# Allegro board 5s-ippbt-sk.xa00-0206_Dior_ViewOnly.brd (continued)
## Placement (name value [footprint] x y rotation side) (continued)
PR236  -  [MX_R0402_SMALL_T01]  100.17 67.88 270 top
PR237  -  [MX_R0402_SMALL_T01]  99.43 64.37 90 bottom
PR238  -  [MX_R0402_SMALL_T01]  99.66 64.83 0 top
PR239  -  [MX_R0402_SMALL_T01]  97.63 79.31 0 bottom
PR240  -  [MX_R0402_SMALL_T01]  99.15 67.88 90 top
PR241  -  [MX_R0402_SHORT_SMALL]  98.01 64.19 0 bottom
PR242  -  [MX_R0402_SMALL_T01]  97.5 60.89 90 top
PR243  -  [MX_R0402_SMALL_T01]  101.95 64.32 270 top
PR244  -  [MX_R0402_SMALL_T01]  96.87 57.82 270 top
PR245  -  [MX_R0402_SMALL_T01]  101.44 65.57 180 top
PR247  -  [MX_R0402_SMALL_T01]  57.88 32.95 90 bottom
PRT1  -  [MX_R0402_SMALL_T01]  108.04 38.79 0 bottom
PRT2  -  [MX_R0402_SMALL_T01]  105 95.44 180 bottom
PRT3  -  [MX_R0402_SMALL_T01]  42 27.11 270 bottom
PRT4  -  [MX_R0402_SMALL_T01]  66.39 42.86 180 bottom
PRT5  -  [MX_R0402_SMALL_T01]  70.71 24.57 0 top
PT1  -  [MX_TPC26T_S4_68]  104.3 109.55 0 top
PT2  -  [MX_TPC26T_S4_68]  107.65 109.76 0 top
PT3  -  [MX_TPC26T_S4_68]  102.58 109.24 0 top
PT4  -  [MX_TPC26T_S4_68]  105.94 110.12 0 top
PT5  -  [MX_TPC26T_S4_68]  100.91 109.71 0 top
PT6  -  [MX_TPC26T_S4_68]  103.26 100.72 180 bottom
PT7  -  [MX_TPC26T_S4_68]  103.29 105.44 180 bottom
PT8  -  [MX_TPC26T_S4_68]  103.27 102.98 180 bottom
PT9  -  [MX_TPC26T_S4_68]  104.59 104.2 180 bottom
PT10  -  [MX_TPC26T_S4_68]  104.61 101.81 180 bottom
PU1  -  [MX_SOT89]  107.03 97.21 180 top
PU2  -  [MX_DFN_10P_20_S118_P_RI_2V]  97.5 103.06 180 top
PU3  -  [MX_QFN_20P_16_S118_PAD_4V]  13.3 32.83 270 bottom
PU4  -  [MX_SOIC_8P_50_197X236_PAD_R]  42.77 12.76 90 bottom
PU5  -  [MX_SOIC_8P_50_197X236_PAD_R]  99.15 19.74 90 bottom
PU6  -  [MX_SOIC_8P_50_197X236_PAD_R]  64.48 33.97 90 bottom
PU7  -  [MX_SO8_H69]  40.1 20.25 90 bottom
PU8  -  [MX_QFN_20P_16_S118_PAD_4V]  12.54 77.4 180 bottom
PU9  -  [MX_QFN_32P_16_S157_PAD_4V]  100.8 60.26 90 bottom
Q1  -  [MX_SOT23_H43]  19.78 59.88 180 bottom
Q2  -  [MX_SOT23_H43]  19.78 56.57 180 bottom
Q3  -  [MX_SOT363]  19.52 69.66 270 bottom
Q7  -  [MX_SOT23]  80.36 31.68 90 bottom
Q9  -  [MX_SOT23]  26.13 63.31 180 bottom
Q27  -  [MX_SOT23_TOREX_H57]  57.75 93.02 0 top
Q30  -  [MX_SOT23]  107.15 13.01 90 top
Q31  -  [MX_SOT23]  101.31 14.92 90 top
Q32  -  [MX_SOT23]  93.44 15.17 90 top
Q33  -  [MX_SOT23]  96.74 15.17 90 top
Q38  -  [MX_SOT23_H43]  64.74 81.47 90 top
Q39  -  [MX_SOT23_H43]  61.18 81.4 90 top
Q41  -  [MX_SOT23]  45.69 26.6 270 bottom
Q9414  -  [MX_SOT23_H43]  26.13 73.34 180 bottom
Q9415  -  [MX_SOT23_H43]  48.99 26.6 270 bottom
Q9416  -  [MX_SOT23_H43]  26.13 80.07 180 bottom
R1  -  [MX_R0402_SMALL_T01]  48.23 32.7 90 bottom
R2  -  [MX_R0402_SMALL_T01]  22.83 70.29 180 bottom
R3  -  [MX_R0402_SMALL_T01]  16.35 70.29 180 bottom
R4  -  [MX_R0402_SMALL_T01]  16.48 58.99 180 bottom
R5  -  [MX_R0402_SMALL_T01]  8.2 94.29 90 top
R6  -  [MX_R0402_SMALL_T01]  60.29 88.07 180 bottom
R7  -  [MX_R0402_SMALL_T01]  80.36 34.73 270 bottom
R8  -  [MX_R0402_SMALL_T01]  22.83 65.9 0 bottom
R9  -  [MX_R0402_SMALL_T01]  22.83 67.67 0 bottom
R10  -  [MX_R0402_SMALL_T01]  64.04 83.27 270 bottom
R11  -  [MX_R0402_SMALL_T01]  64.89 83.27 270 bottom
R13  -  [MX_R0402_SMALL_T01]  60.29 88.96 180 bottom
R14  -  [MX_R0402_SMALL_T01]  11.68 109.56 0 top
R15  -  [MX_R0402_SMALL_T01]  11.68 107.83 0 top
R16  -  [MX_R0402_SMALL_T01]  58.11 85.15 180 bottom
R17  -  [MX_R0402_SMALL_T01]  58.11 86.17 180 bottom
R18  -  [MX_R0402_SMALL_T01]  67.66 83.04 270 bottom
R19  -  [MX_R0402_SMALL_T01]  60.29 85.15 0 bottom
R20  -  [MX_R0402_SMALL_T01]  60.29 86.17 0 bottom
R21  -  [MX_R0402_SMALL_T01]  66.77 83.04 90 bottom
R22  -  [MX_R0402_SMALL_T01]  68.17 92.77 90 bottom
R23  -  [MX_R0402_SMALL_T01]  70.58 85.78 0 bottom
R24  -  [MX_R0402_SMALL_T01]  70.58 86.67 0 bottom
R25  -  [MX_R0402_SMALL_T01]  70.58 88.39 0 bottom
R26  -  [MX_R0402_SMALL_T01]  71.21 89.62 270 bottom
R30  -  [MX_R0402_SMALL_T01]  83.02 18.35 270 top
R89  -  [MX_R0402_SMALL_T01]  70.71 4.89 0 top
R90  -  [MX_R0402_SMALL_T01]  61.94 93.02 270 top
R91  -  [MX_R0402_SMALL_T01]  62.83 93.02 90 top
R92  -  [MX_R0603_SHORT_SMALL]  58.13 93.79 180 bottom
R93  -  [MX_R0402_SMALL_T01]  53.05 101.15 90 bottom
R95  -  [MX_R0402_SMALL_T01]  60.04 96.96 0 bottom
R96  -  [MX_R0402_SMALL_T01]  57.88 95.94 180 bottom
R97  -  [MX_R0402_SMALL_T01]  57.88 96.96 180 bottom
R109  -  [MX_R0402_SMALL_T01]  4.4 94.76 0 top
R149  -  [MX_R0402_SMALL_T01]  108.55 41.08 90 bottom
R153  -  [MX_R0402_SMALL_T01]  93.31 74.74 180 top
R159  -  [MX_R0402_SMALL_T01]  105.12 11.87 270 top
R160  -  [MX_R0402_SMALL_T01]  104.23 11.87 270 top
R169  -  [MX_R0402_SMALL_T01]  103.34 11.87 270 top
R170  -  [MX_R0402_SMALL_T01]  102.46 11.87 270 top
R176  -  [MX_R0402_SMALL_T01]  90.9 13.52 0 top
R182  -  [MX_R0402_SMALL_T01]  90.9 14.41 0 top
R184  -  [MX_R0402_SMALL_T01]  99.03 16.19 270 top
R188  -  [MX_R0402_SMALL_T01]  4.92 44.76 0 bottom
R191  -  [MX_R0402_SMALL_T01]  68.04 9.84 0 top
R192  -  [MX_R0402_SMALL_T01]  70.68 6.18 0 top
R197  -  [MX_R0402_SHORT_SMALL]  9.24 52.89 90 bottom
R198  -  [MX_R1206]  9.75 66.23 0 bottom
R199  -  [MX_R0402_SHORT_SMALL]  11.65 61.91 270 bottom
R200  -  [MX_R0402_SMALL_T01]  6.44 61.4 0 bottom
R205  -  [MX_R0603_SMALL_T01]  82.24 4.4 0 bottom
R207  -  [MX_R0402_SHORT_SMALL]  67.02 27.24 180 bottom
R209  -  [MX_R0603_SMALL_T01]  66.77 28.38 0 bottom
R212  -  [MX_R0402_SHORT_SMALL]  84.55 15.6 0 bottom
R213  -  [MX_R0402_SHORT_SMALL]  79.21 28.38 90 bottom
R214  -  [MX_R0402_SMALL_T01]  80.1 28.38 90 bottom
R215  -  [MX_R0402_SMALL_T01]  84.17 11.11 0 bottom
R216  -  [MX_R0402_SHORT_SMALL]  84.17 12.12 180 bottom
R221  -  [MX_R0402_SMALL_T01]  84.55 21.14 180 bottom
R222  -  [MX_R0402_SMALL_T01]  84.55 18.47 180 bottom
R224  -  [MX_R0402_SMALL_T01]  84.55 20.25 180 bottom
R225  -  [MX_R0402_SMALL_T01]  81.15 6.33 270 bottom
R226  -  [MX_R0402_SMALL_T01]  75.02 11.49 180 top
R227  -  [MX_R0402_SMALL_T01]  88.1 21.9 180 bottom
R228  -  [MX_R0402_SMALL_T01]  90.01 21.9 0 bottom
R229  -  [MX_SHORTPIN_RECTANGLE_LF3]  93.82 13.01 0 bottom
R230  -  [MX_R0402_SMALL_T01]  88.49 13.01 0 bottom
R233  -  [MX_R0402_SMALL_T01]  74.64 22.79 270 top
R234  -  [MX_R0402_SMALL_T01]  72.86 22.79 270 top
R243  -  [MX_R0402_SMALL_T01]  84.55 19.36 180 bottom
R244  -  [MX_R0402_SMALL_T01]  73.37 95.44 270 top
R250  -  [MX_R0402_SHORT_SMALL]  75.02 76.77 90 top
R251  -  [MX_R0402_SMALL_T01]  65.02 85.28 180 top
R252  -  [MX_R0402_SMALL_T01]  48.73 23.92 0 bottom
R330  -  [MX_R0402_SMALL_T01]  106.9 16.06 90 top
R332  -  [MX_R0402_SMALL_T01]  103.34 14.28 270 top
R357  -  [MX_R0402_SMALL_T01]  105.12 14.28 270 top
R368  -  [MX_R0402_SMALL_T01]  105.12 16.06 90 top
R370  -  [MX_R0402_SMALL_T01]  106.01 16.06 90 top
R371  -  [MX_R0402_SMALL_T01]  104.23 14.28 270 top
R3008  -  [MX_R0402_SMALL_T01]  73.5 28.25 270 bottom
R60208  -  [MX_R0402_SMALL_T01]  61.94 85.4 0 top
R60209  -  [MX_R0402_SMALL_T01]  61.94 84.51 0 top
R60212  -  [MX_R0402_SHORT_SMALL]  84.55 16.44 0 bottom
R60214  -  [MX_R0402_SMALL_T01]  4.92 43.87 0 bottom
R60215  -  [MX_R0402_SHORT_SMALL]  71.47 11.87 90 top
R60216  -  [MX_R0402_SMALL_T01]  18.9 31.07 90 bottom
R60217  -  [MX_R0402_SMALL_T01]  21.25 35.62 270 bottom
R60218  -  [MX_R0402_SMALL_T01]  82.9 40.57 270 top
R60219  -  [MX_R0402_SMALL_T01]  82.9 42.35 270 top
R60220  -  [MX_R0402_SMALL_T01]  69.82 40.45 270 top
R60221  -  [MX_R0402_SMALL_T01]  70.71 40.45 90 top
R60226  -  [MX_R0402_SMALL_T01]  22.83 66.79 0 bottom
R60290  -  [MX_R0402_SMALL_T01]  66.39 79.56 0 bottom
R60291  -  [MX_R0402_SHORT_SMALL]  63.39 8.7 180 bottom
R60293  -  [MX_R0402_SHORT_SMALL]  70.07 6.41 270 bottom
R60297  -  [MX_R0402_SMALL_T01]  22.95 32.32 0 bottom
R60298  -  [MX_R0402_SMALL_T01]  16.35 63.05 0 bottom
R60299  -  [MX_R0402_SMALL_T01]  22.83 62.42 0 bottom
R60302  -  [MX_R0402_SMALL_T01]  22.83 79.18 180 bottom
R60304  -  [MX_R0402_SMALL_T01]  22.83 56.12 0 bottom
R60306  -  [MX_R0402_SMALL_T01]  22.83 49.08 0 bottom
R60307  -  [MX_R0402_SMALL_T01]  21.43 31.12 90 bottom
R60308  -  [MX_R0402_SMALL_T01]  20.77 38.9 180 bottom
R60309  -  [MX_R0402_SMALL_T01]  22.83 75.88 180 bottom
R60310  -  [MX_R0402_SMALL_T01]  60.29 87.23 180 bottom
SC1  -  [MX_C0402_SMALL_T01]  90.14 54.42 90 top
SC2  -  [MX_C0402_SMALL_T01]  4.92 42.99 180 bottom
SC3  -  [MX_C0402_SMALL_T01]  90.52 58.23 180 top
SC4  -  [MX_C0402_SMALL_T01]  85.08 74.69 270 bottom
SC5  -  [MX_C0402_SMALL_T01]  84.29 77.66 180 bottom
SC6  -  [MX_C0402_SMALL_T01]  86.56 76.51 180 bottom
SC7  -  [MX_C0402_SMALL_T01]  22.95 34.73 0 bottom
SC8  -  [MX_C0402_SMALL_T01]  16.35 64.7 0 bottom
SC9  -  [MX_C0402_SMALL_T01]  87.85 52.51 0 top
SC10  -  [MX_C0402_SMALL_T01]  87.85 53.4 0 top
SC11  -  [MX_C0402_SMALL_T01]  52.54 28.38 90 top
SC12  -  [MX_C0402_SMALL_T01]  43.63 28.38 0 top
SC13  -  [MX_C0402_SMALL_T01]  53.31 24.95 180 top
SC14  -  [MX_C0402_SMALL_T01]  44.19 25.31 0 top
SC21  -  [MX_C0402_SMALL_T01]  4.41 58.35 0 bottom
SC22  -  [MX_C0402_SMALL_T01]  4.41 59.24 0 bottom
SC23  -  [MX_C0402_SMALL_T01]  86.45 13.01 180 bottom
SC24  -  [MX_C0402_SMALL_T01]  70.96 6.41 90 bottom
SC25  -  [MX_C0402_SMALL_T01]  72.97 6.44 90 bottom
SC26  -  [MX_C0402_SMALL_T01]  73.25 11.87 90 top
SC27  -  [MX_C0402_SMALL_T01]  74.19 76.77 270 top
SC33  -  [MX_C0402_SMALL_T01]  73.25 76.77 270 top
SC36  -  [MX_C0402_SMALL_T01]  22.83 59.11 0 bottom
SC65  -  [MX_C0402_SMALL_T01]  22.83 52.84 0 bottom
SC67  -  [MX_C0402_SMALL_T01]  22.83 60 0 bottom
SD1  -  [MX_SOT323]  5.3 40.83 270 bottom
SL1  -  [MX_R0603_SHORT_SMALL]  83.02 40.32 270 bottom
SL2  -  [MX_R0603_SHORT_SMALL]  64.52 40.32 270 top
SL3  -  [MX_R0603_SHORT_SMALL]  78.01 40.32 270 top
SL4  -  [MX_R0603_SHORT_SMALL]  71.77 50.02 180 top
SL5  -  [MX_R0603_SHORT_SMALL]  66.96 40.32 270 top
SL6  -  [MX_R0603_SHORT_SMALL]  90.52 61.91 180 bottom
SL7  -  [MX_R0603_SHORT_SMALL]  68.67 40.32 270 top
SL8  -  [MX_R0603_SHORT_SMALL]  90.52 60.64 0 bottom
SL9  -  [MX_R0603_SMALL_T01]  75.66 40.32 270 top
SL10  -  [MX_R0603_SMALL_T01]  73.12 40.32 270 top
SL11  -  [MX_R0603_SHORT_SMALL]  86.3 64.98 0 top
SL12  -  [MX_R0603_SMALL_T01]  65.74 40.32 270 top
SL13  -  [MX_R0603_SHORT_SMALL]  85.31 40.32 270 bottom
SL14  -  [MX_R0603_SHORT_SMALL]  74.13 59.11 270 top
SL15  -  [MX_R0603_SMALL_T01]  74.39 40.32 90 top
SL16  -  [MX_R0603_SHORT_SMALL]  78.58 62.42 180 top
SM_TP1  -  [MX_TPC26T_S4_68]  65.27 81.7 180 bottom
SR1  -  [MX_R0402_SMALL_T01]  50.41 29.9 90 bottom
SR2  -  [MX_R0402_SMALL_T01]  64.74 78.42 90 top
SR3  -  [MX_R0402_SMALL_T01]  75.15 95.18 180 bottom
SR4  -  [MX_R0402_SMALL_T01]  72.61 97.47 180 bottom
SR5  -  [MX_R0402_SMALL_T01]  49.88 32.7 270 bottom
SR6  -  [MX_R0402_SMALL_T01]  49.06 32.7 90 bottom
SR7  -  [MX_R0402_SMALL_T01]  46.19 32.7 270 bottom
SR8  -  [MX_R0402_SMALL_T01]  45.18 32.7 270 bottom
SR9  -  [MX_R0402_SMALL_T01]  44.16 32.7 90 bottom
SR10  -  [MX_R0402_SMALL_T01]  47.97 29.9 90 bottom
SR11  -  [MX_R0402_SMALL_T01]  46.96 29.9 90 bottom
SR12  -  [MX_R0402_SMALL_T01]  93.69 93.53 180 top
SR13  -  [MX_R0402_SMALL_T01]  93.69 94.42 0 top
SR14  -  [MX_R0402_SMALL_T01]  76.42 89.47 270 top
SR15  -  [MX_R0402_SMALL_T01]  16.35 69.4 180 bottom
SR16  -  [MX_R0402_SMALL_T01]  75.53 89.47 270 top
SR18  -  [MX_R0603_SMALL_T01]  90.39 59.88 270 top
SR21  -  [MX_R0402_SMALL_T01]  91.1 55.03 180 bottom
SR22  -  [MX_R0402_SMALL_T01]  90.52 57.03 180 bottom
SR24  -  [MX_R0402_SMALL_T01]  91.13 54.19 180 bottom
SR26  -  [MX_R0402_SMALL_T01]  90.52 57.9 180 bottom
SR28  -  [MX_R0402_SMALL_T01]  22.83 72.45 0 bottom
SR29  -  [MX_R0402_SMALL_T01]  22.83 73.34 180 bottom
SR30  -  [MX_R0402_SMALL_T01]  90.14 56.07 90 top
SR31  -  [MX_R0402_SMALL_T01]  90.52 57.34 0 top
SR32  -  [MX_R0402_SMALL_T01]  90.52 58.73 180 bottom
SR33  -  [MX_R0402_SMALL_T01]  90.52 59.62 180 bottom
SR34  -  [MX_R0402_SMALL_T01]  22.83 55.23 180 bottom
SR35  -  [MX_R0402_SHORT_SMALL]  22.83 74.23 0 bottom
SR36  -  [MX_R0402_SMALL_T01]  74.13 78.88 270 top
SR37  -  [MX_R0402_SMALL_T01]  75.91 78.88 270 top
SR41  -  [MX_R0402_SMALL_T01]  86.96 74.61 90 bottom
SR43  -  [MX_R0603_SMALL_T01]  71.98 77.02 90 bottom
SR44  -  [MX_R0402_SMALL_T01]  70.83 76.89 90 bottom
SR46  -  [MX_R0402_SMALL_T01]  81.93 76.77 90 bottom
SR47  -  [MX_R0402_SMALL_T01]  90.52 66.61 0 bottom
SR48  -  [MX_R0402_SMALL_T01]  73.7 76.77 90 bottom
SR49  -  [MX_R0402_SMALL_T01]  90.52 67.5 180 bottom
SR50  -  [MX_R0402_SMALL_T01]  74.59 76.77 90 bottom
SR52  -  [MX_R0402_SMALL_T01]  76.34 76.56 90 bottom
SR54  -  [MX_R0402_SMALL_T01]  75.48 76.56 90 bottom
SR55  -  [MX_R0402_SMALL_T01]  79.24 78.93 270 bottom
SR56  -  [MX_R0402_SMALL_T01]  77.56 78.93 90 bottom
SR57  -  [MX_R0402_SMALL_T01]  80.99 78.93 90 bottom
SR58  -  [MX_R0402_SMALL_T01]  78.4 78.93 90 bottom
SR59  -  [MX_R0402_SMALL_T01]  78.21 76.5 90 bottom
SR60  -  [MX_R0402_SMALL_T01]  80.15 76.77 90 bottom
SR61  -  [MX_R0402_SMALL_T01]  77.4 76.5 90 bottom
SR62  -  [MX_R0603_SMALL_T01]  78.99 76.46 90 top
SR63  -  [MX_R0603_SMALL_T01]  84.42 76.51 180 bottom
SR64  -  [MX_R0402_SMALL_T01]  86.56 77.66 0 bottom
SR65  -  [MX_R0402_SMALL_T01]  22.95 33.84 0 bottom
SR66  -  [MX_R0402_SMALL_T01]  22.95 35.75 0 bottom
SR67  -  [MX_R0402_SMALL_T01]  19.5 38.44 270 bottom
SR68  -  [MX_R0402_SMALL_T01]  18.15 38.44 270 bottom
SR71  -  [MX_R0402_SMALL_T01]  16.35 65.59 0 bottom
SR72  -  [MX_R0402_SMALL_T01]  16.35 66.48 0 bottom
SR74  -  [MX_R0402_SMALL_T01]  83.79 40.57 270 top
SR76  -  [MX_R0603_SMALL_T01]  78.4 46.54 270 top
SR77  -  [MX_R0402_SMALL_T01]  81.22 41.18 90 top
SR78  -  [MX_R0402_SMALL_T01]  80.38 41.84 90 top
SR79  -  [MX_R0402_SMALL_T01]  82.06 41.18 90 top
SR80  -  [MX_R0402_SMALL_T01]  85.82 45.27 180 top
SR81  -  [MX_R0402_SMALL_T01]  81.5 34.73 270 bottom
SR82  -  [MX_R0402_SMALL_T01]  85.82 46.16 180 top
SR83  -  [MX_R0402_SMALL_T01]  85.82 47.05 180 top
SR84  -  [MX_R0603_SMALL_T01]  78.3 54.52 0 top
SR85  -  [MX_R0402_SMALL_T01]  69.94 40.52 90 bottom
SR86  -  [MX_R0402_SMALL_T01]  69.05 40.52 90 bottom
SR87  -  [MX_R0402_SMALL_T01]  68.17 40.52 90 bottom
SR88  -  [MX_R0402_SHORT_SMALL]  71.72 40.52 90 bottom
SR89  -  [MX_R0402_SMALL_T01]  70.83 40.52 90 bottom
SR90  -  [MX_R0402_SMALL_T01]  74.44 47.68 180 top
SR91  -  [MX_R0402_SMALL_T01]  87.22 61.4 270 top
SR94  -  [MX_R0402_SMALL_T01]  78.73 78.9 270 top
SR95  -  [MX_R0402_SMALL_T01]  77.91 78.9 270 top
SR96  -  [MX_R0402_SMALL_T01]  82.77 71.31 0 top
SR97  -  [MX_R0402_SMALL_T01]  82.77 70.42 0 top
SR98  -  [MX_R0402_SMALL_T01]  82.77 69.53 0 top
SR100  -  [MX_R0402_SMALL_T01]  75.66 40.57 270 bottom
SR101  -  [MX_R0402_SMALL_T01]  73.88 40.57 270 bottom
SR102  -  [MX_R0402_SMALL_T01]  77.44 40.57 270 bottom
SR103  -  [MX_R0402_SMALL_T01]  79.88 42.17 270 bottom
SR104  -  [MX_R0402_SMALL_T01]  72.99 40.57 270 bottom
SR105  -  [MX_R0402_SMALL_T01]  76.8 40.57 270 top
SR106  -  [MX_R0402_SMALL_T01]  76.55 40.57 270 bottom
SR107  -  [MX_R0402_SHORT_SMALL]  79.21 40.57 270 bottom
SR108  -  [MX_R0402_SHORT_SMALL]  74.77 40.57 270 bottom
SR109  -  [MX_R0402_SMALL_T01]  53.31 26.6 180 top
SR110  -  [MX_R0402_SMALL_T01]  53.31 30.79 180 top
SR111  -  [MX_R0402_SMALL_T01]  53.31 29.97 180 top
SR112  -  [MX_R0402_SMALL_T01]  44.16 30.67 0 top
SR113  -  [MX_R0402_SMALL_T01]  53.31 31.68 180 top
SR114  -  [MX_R0402_SMALL_T01]  44.16 29.27 0 top
SR115  -  [MX_R0402_SMALL_T01]  42 29.6 180 top
SR116  -  [MX_R0402_SMALL_T01]  42 30.67 180 top
SR117  -  [MX_R0402_SMALL_T01]  39.9 29.12 180 top
SR118  -  [MX_R0402_SMALL_T01]  39.84 30.67 180 top
SR119  -  [MX_R0402_SMALL_T01]  44.54 26.6 0 top
SR120  -  [MX_R0402_SMALL_T01]  44.85 28 270 top
SR121  -  [MX_R0402_SMALL_T01]  42 26.32 180 top
SR122  -  [MX_R0402_SMALL_T01]  42 27.47 180 top
SR123  -  [MX_R0402_SMALL_T01]  42.1 32.95 90 top
SR124  -  [MX_R0402_SMALL_T01]  38.45 31.94 90 top
SR134  -  [MX_R0402_SMALL_T01]  4.4 95.72 0 top
SR147  -  [MX_R0402_SHORT_SMALL]  13.56 55.81 180 bottom
SR148  -  [MX_R0402_SHORT_SMALL]  13.56 54.92 180 bottom
SR149  -  [MX_R0402_SHORT_SMALL]  13.56 56.7 180 bottom
SR150  -  [MX_R0402_SHORT_SMALL]  13.56 58.48 180 bottom
SR151  -  [MX_R0402_SHORT_SMALL]  13.56 60.41 180 bottom
SR152  -  [MX_R0402_SHORT_SMALL]  84.17 13.01 0 bottom
SR153  -  [MX_R0402_SHORT_SMALL]  72.36 11.87 90 top
SR154  -  [MX_R0402_SMALL_T01]  9.75 37.78 90 bottom
SR156  -  [MX_R0402_SMALL_T01]  80.1 78.93 90 bottom
SR157  -  [MX_R0402_SMALL_T01]  81.88 78.93 90 bottom
SR158  -  [MX_R0402_SMALL_T01]  80.99 76.77 90 bottom
SR159  -  [MX_R0402_SMALL_T01]  79.27 76.77 90 bottom
SR163  -  [MX_R0402_SMALL_T01]  39.84 31.56 0 top
SR167  -  [MX_R0402_SMALL_T01]  90.52 65.72 0 bottom
SR170  -  [MX_R0402_SMALL_T01]  90.52 64.83 0 bottom
SR171  -  [MX_R0402_SMALL_T01]  90.52 63.94 0 bottom
SR172  -  [MX_R0402_SMALL_T01]  86 74.69 90 bottom
SR182  -  [MX_R0402_SMALL_T01]  87.85 66.73 0 top
SR183  -  [MX_R0402_SMALL_T01]  90.52 63.05 0 bottom
SR184  -  [MX_R0402_SMALL_T01]  90.52 68.39 0 bottom
SR185  -  [MX_R0402_SMALL_T01]  79.98 78.93 90 top
SR188  -  [MX_R0402_SMALL_T01]  78.33 40.57 270 bottom
SR193  -  [MX_R0402_SMALL_T01]  86.33 61.4 270 top
SR196  -  [MX_R0402_SMALL_T01]  75.02 78.88 270 top
SR624  -  [MX_R0402_SMALL_T01]  22.83 60.89 0 bottom
SR625  -  [MX_R0402_SMALL_T01]  22.83 58.23 0 bottom
SR626  -  [MX_R0603_SMALL_T01]  71.85 40.32 270 top
SR627  -  [MX_R0603_SMALL_T01]  79.37 40.32 90 top
SR640  -  [MX_R0402_SMALL_T01]  81.91 41.16 90 bottom
SR641  -  [MX_R0402_SMALL_T01]  76.78 78.65 270 top
SR642  -  [MX_R0402_SMALL_T01]  73.2 78.88 270 top
SR653  -  [MX_R0402_SMALL_T01]  86.45 40.57 90 top
SR654  -  [MX_R0402_SMALL_T01]  84.68 40.57 90 top
SR655  -  [MX_R0402_SMALL_T01]  85.56 40.57 90 top
SR656  -  [MX_R0402_SMALL_T01]  87.34 40.57 90 top
SR659  -  [MX_R0402_SMALL_T01]  75.15 6.41 270 bottom
SR662  -  [MX_R0402_SMALL_T01]  22.83 69.02 0 bottom
SR663  -  [MX_R0402_SMALL_T01]  46.37 24.04 0 bottom
SR664  -  [MX_R0402_SMALL_T01]  16.35 62.16 180 bottom
SR665  -  [MX_R0402_SMALL_T01]  22.95 31.43 180 bottom
SR670  -  [MX_R0402_SMALL_T01]  22.83 51.95 0 bottom
SR671  -  [MX_R0402_SMALL_T01]  16.48 53.27 0 bottom
SR672  -  [MX_R0402_SMALL_T01]  66.51 4.5 0 top
SR673  -  [MX_R0402_SMALL_T01]  66.51 3.62 0 top
SR674  -  [MX_R0402_SMALL_T01]  66.51 2.73 0 top
SSC3  -  [MX_C0402_SMALL_T01]  112.36 18.98 90 top
SSC4  -  [MX_C0402_SMALL_T01]  111.4 37.77 270 top
SSC5  -  [MX_C0603_SMALL_T01]  110.76 19.64 0 bottom
SSC19  -  [MX_C0402_SMALL_T01]  118.79 15.81 270 top
SSC20  -  [MX_C0402_SMALL_T01]  119.6 15.81 270 top
SSC21  -  [MX_C0402_SMALL_T01]  117.06 15.81 270 top
SSC22  -  [MX_C0402_SMALL_T01]  117.95 15.81 270 top
SSC23  -  [MX_C0402_SMALL_T01]  112.23 37.77 270 top
ST1  -  [MX_TPC26T_S4_68]  83.89 55.89 0 top
ST2  -  [MX_TPC26T_S4_68]  85.72 55.66 0 top
ST3  -  [MX_TPC26T_S4_68]  70.53 74.38 180 bottom
ST4  -  [MX_TPC26B_S4_68]  99.85 51.85 0 top
ST5  -  [MX_TPC26B_S4_68]  67.15 77.66 0 top
ST6  -  [MX_TPC26B_S4_68]  65.5 78.5 0 top
ST7  -  [MX_TPC26B_S4_68]  61.94 11.87 0 top
ST18  -  [MX_TPC26B_S4_68]  68.83 76.51 0 top
ST19  -  [MX_TPC26B_S4_68]  68.12 79.51 0 top
ST20  -  [MX_TPC26B_S4_68]  88.23 65.24 180 bottom
ST22  -  [MX_TPC26B_S4_68]  86.2 63.31 0 top
ST23  -  [MX_TPC26B_S4_68]  88.47 67.7 0 top
ST24  -  [MX_TPC26B_S4_68]  80.69 73.29 0 top
ST25  -  [MX_TPC26B_S4_68]  77.46 7.86 180 bottom
ST29  -  [MX_TPC26B_S4_68]  76.8 71.79 180 bottom
ST30  -  [MX_TPC26B_S4_68]  89.12 64.02 0 top
ST49  -  [MX_TPC26B_S4_68]  76.93 25.08 180 bottom
ST50  -  [MX_TPC26B_S4_68]  68.47 6.36 0 top
ST52  -  [MX_TPC26B_S4_68]  63.59 10.82 270 top
ST61  -  [MX_TPC26B_S4_68]  78.73 13.37 180 bottom
ST69  -  [MX_TPC26B_S4_68]  86.45 42.55 180 bottom
ST70  -  [MX_TPC26B_S4_68]  83.53 44.64 180 bottom
ST71  -  [MX_TPC26B_S4_68]  87.24 46.08 180 bottom
ST72  -  [MX_TPC26B_S4_68]  67.78 42.91 0 top
ST73  -  [MX_TPC26B_S4_68]  66.4 40.67 0 top
ST77  -  [MX_TPC26B_S4_68]  71.98 6.79 0 top
ST78  -  [MX_TPC26B_S4_68]  76.67 69.07 180 bottom
ST79  -  [MX_TPC26B_S4_68]  80.99 22.16 180 bottom
ST80  -  [MX_TPC26B_S4_68]  78.31 48.56 180 bottom
ST81  -  [MX_TPC26B_S4_68]  90.04 64.25 180 bottom
ST82  -  [MX_TPC26B_S4_68]  84.17 14.03 0 top
ST83  -  [MX_TPC26B_S4_68]  74.08 26.76 180 bottom
ST84  -  [MX_TPC26B_S4_68]  79.65 6.46 0 top
ST85  -  [MX_TPC26B_S4_68]  78.22 70.52 180 bottom
ST86  -  [MX_TPC26B_S4_68]  78.62 65.74 180 bottom
ST87  -  [MX_TPC26B_S4_68]  77.31 67.37 180 bottom
ST88  -  [MX_TPC26B_S4_68]  78.76 68.84 180 bottom
ST89  -  [MX_TPC26B_S4_68]  75.28 67.5 180 bottom
SW10  -  [TP_SW_4P_4HOLD_DIPTRON]  101.95 7.81 0 top
T1C1  -  [MX_C0402_SMALL_T01]  11.17 24.95 0 top
T1C3  -  [MX_C0603_SMALL_T02]  13.71 21.07 90 bottom
T1C4  -  [MX_C0402_SMALL_T01]  11.8 20.86 270 bottom
T1C13  -  [MX_C0402_SMALL_T01]  11.17 25.84 0 top
T1C14  -  [MX_C0402_SMALL_T01]  11.17 23.19 0 top
T1C15  -  [MX_C0402_SMALL_T01]  11.17 24.06 0 top
T1C17  -  [MX_C0402_SMALL_T01]  12.64 20.86 270 bottom
TPC1  -  [MX_C0402_SMALL_T01]  88.92 23.68 90 bottom
TPC2  -  [MX_C0402_SMALL_T01]  88.87 34.73 270 bottom
TPC3  -  [MX_C0402_SMALL_T01]  85.31 34.73 270 bottom
TPC4  -  [MX_C0402_SMALL_T01]  85.69 23.68 90 bottom
TPR1  -  [MX_R0402_SMALL_T01]  86.2 34.73 270 bottom
TPR2  -  [MX_R0402_SMALL_T01]  87.09 34.73 90 bottom
TPR3  -  [MX_R0402_SMALL_T01]  86.71 23.68 270 bottom
TPR4  -  [MX_R0402_SMALL_T01]  83.79 23.68 90 bottom
TPR5  -  [MX_R0402_SMALL_T01]  87.98 34.73 90 bottom
TPU1  -  [MX_SOIC_28P_26_386X252_H43]  87.34 29.14 0 bottom
U1  -  [MX_SOT363_PHILIPS]  19.47 35.54 180 bottom
U3  -  [MX_SOIC_8P_26_122X193]  48.73 29.78 90 top
U4  -  [MX_SOIC_8P_26_122X193]  48.73 25.97 90 top
U14  -  [MX_SOIC_8P_26_122X193_PA_TI]  103.85 42.48 90 bottom
U18  -  [MX_SOIC_8P_26_122X193_PA_TI]  70.96 95.18 0 top
U19  -  [MX_SOT23_S6]  61.18 102.17 270 bottom
U23  -  [MX_QFN_24P_20_S157_PAD_T_4V]  9.11 57.46 90 bottom
U24  -  [MX_QFP_128P_16_630X630]  73.12 17.2 180 bottom
U25  -  [MX_SOIC_8P_50_197X236]  89.76 17.46 0 bottom
UC1  -  [MX_C0402_SMALL_T01]  104.61 46.54 180 bottom
UC2  -  [MX_C0402_SMALL_T01]  104.61 47.43 180 bottom
UC3  -  [MX_C0402_SMALL_T01]  57.75 102.68 0 top
UC4  -  [MX_C0402_SMALL_T01]  57.75 103.56 0 top
UC5  -  [MX_C0402_SMALL_T01]  70.07 91.37 0 top
UC6  -  [MX_C0402_SMALL_T01]  65.12 100.39 0 bottom
UC7  -  [MX_C0402_SMALL_T01]  65.12 101.79 0 bottom
UC8  -  [MX_C0402_SMALL_T01]  65.12 104.07 0 bottom
UC9  -  [MX_C0402_SMALL_T01]  65.12 102.68 0 bottom
UC10  -  [MX_C0603_SMALL_T01]  57.75 101.66 180 top
UC11  -  [MX_C0402_SMALL_T01]  106.72 48.22 90 top
UC12  -  [MX_C0402_SMALL_T01]  104.36 73.97 0 bottom
UC13  -  [MX_C0402_SMALL_T01]  104.36 72.83 0 bottom
UC14  -  [MX_C0402_SMALL_T01]  104.36 76.01 0 bottom
UC15  -  [MX_C0402_SMALL_T01]  104.36 74.86 0 bottom
UCE1  -  [CESMD_260X260_SMD124X74]  103.98 43.75 270 top
UR1  -  [MX_R0402_SMALL_T01]  105.38 44.89 0 bottom
UR3  -  [MX_R0402_SMALL_T01]  99.92 42.99 90 bottom
UR7  -  [MX_R0402_SMALL_T01]  71.72 91.37 0 top
UU1  -  [MX_ESD_10P_20_98X39_NXP]  106.93 47.68 90 bottom
UU2  -  [MX_SOT23_S6]  107.84 74.48 90 bottom
UU3  -  [MX_QFN_28P_20_S197_P_GEN_4V]  65.37 87.94 0 bottom
VF1  -  [MX_POLYSWITCH_2P_0805_H30]  74.9 98.48 270 bottom
WC4  -  [MX_C0402_SMALL_T01]  45.81 4.38 270 bottom
WC5  -  [MX_C0402_SMALL_T01]  44.92 4.38 270 bottom
WC6  -  [MX_C0603_SMALL_T01]  45.81 2.19 270 bottom
WC14  -  [MX_C0402_SMALL_T01]  42.13 8.31 0 top
WC15  -  [MX_C0402_SMALL_T01]  42.66 4.63 270 top
WQ6  -  [MX_SOT363]  51.88 2.45 270 bottom
WR34  -  [MX_R0402_SMALL_T01]  42.13 6.41 0 top
WR35  -  [MX_R0402_SMALL_T01]  42.13 7.3 180 top
WR36  -  [MX_R0402_SMALL_T01]  42.13 9.2 180 top
WR59  -  [MX_R0402_SMALL_T01]  49.42 3.44 0 bottom
WR62  -  [MX_R0402_SMALL_T01]  54.17 3.92 270 bottom
WR64  -  [MX_R0402_SMALL_T01]  49.42 2.6 0 bottom
WR81  -  [MX_R0805_SMALL_T02]  39.49 2.6 270 bottom
WR84  -  [MX_R0402_SMALL_T01]  55.34 7.93 270 top
WT12  -  [MX_TPC26T_S4_68]  41.37 11.87 0 top
WT13  -  [MX_TPC26T_S4_68]  40.48 10.35 0 top
WT14  -  [MX_TPC26T_S4_68]  42.26 10.35 0 top
XBT1  -  [MX_WTOB_2P_49_2H_ACES]  7.52 34.86 270 top
XMM1  -  [MX_DDR3_DIMM_204P_24_4HD_AR]  35.64 61.93 270 bottom
XU1  -  [MX_BGA_1170P_984X1062]  71.3 58.43 0 bottom
Y5  -  [MX_XTAL_2P_126X59_CITIZEN]  85.69 79.43 0 bottom
Y10  -  [MX_XTAL_4P_126X98_HOSON_H35]  50.13 90.74 180 bottom
Y12  -  [MX_XTAL_4P_126X98_HOSON_H35]  92.3 54.8 270 top
Y24  -  [MX_XTAL_4P_126X98_HELE]  73.5 88.6 270 bottom

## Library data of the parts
AC1 AC2 C246 C260 C265 PC29 PC43 PCB1 = DEV_265
AC3 AC4 LANC1 LANC3 LANC4 PC87 PC98 PC161 PC167 = DEV_264
AC5 AC6 C941162 PC27 PC41 PC91 PC103 = DEV_261
AC7 AC51 AC62 C14-C25 C27 C28 C30 C36-C38 C42 C44 C45 C47-C55 C62 C63 C66 C67 C69-C75 C159 C941134-C941139 D3CB1 DCB3-DCB6 DEC4 DEC6 DEC8 PC9 PC53 PC58 PC59 PC78 PC81 SC2 = DEV_107
AC38 AC40 AC42 AC46 AC48 AC54 AC56 AC58 AC60 C56-C61 C65 C82 DCB1 DCB7 DCB21-DCB25 DEC2 PC119-PC121 SSC5 UC10 WC6 = DEV_108
AC39 AC41 AC49 AC55 AC57 AC61 = DEV_263
AC43-AC45 HC14 = DEV_262
AC50 AC52 = DEV_109: room: AUD
AC53 C941140 C941141 C941156 D3CB8 SSC23 T1C17 UC11 WC14 WC15 = DEV_260
AC59 = DEV_259
AC63 C163 C302 CB2 CB3 HC10-HC13 M1C9 M1C10 PC165 SC23-SC26 SC67 = DEV_258
AD1-AD4 = DEV_85
AQ1 AQ2 D1 MQ1 MQ3 MQ6 MQ8 MQ22 MQ25 MQ31 PQ3 PQ12 PQ13 PQ16 PQ19 PQ22 PQ24 PQ25 PQ27 PQ28 PQ32 PQ33 PQ35 PQ43 Q1 Q2 Q38 Q39 Q9414-Q9416 = DEV_13
AQ3 LQ3 MQ5 MQ7 MQ9 MQ23 MQ32 PQ36 PQ38 Q9 Q30-Q33 Q41 = DEV_12
AR1 SR85-SR87 SR89 = DEV_257
AR3 = DEV_256
AR5 AR36 = DEV_255
AR6 AR7 = DEV_271
AR8 PR34 PR97 PR105 R16 = DEV_102
AR10 O2R249 O2R250 PR173 PR175 R8 R10 R11 R13 R19 R20 R23 R24 R95 R184 SR3 SR12 SR56-SR61 SR81 SR96 SR97 SR154 SR156-SR159 SR671 = DEV_103
AR37 SL9 SL10 SL12 SL15 = DEV_254
AR38 = DEV_253
AU1 = DEV_57
C1 C240 C254 C269 PC1 PC26 PC30 PC123 PC125 PC137 = DEV_95
C2 C3 C6-C9 C31-C35 C46 C68 C76-C78 C149-C152 C155-C158 C160-C162 C245 C249 C253 C256 C257 C261-C264 C266-C268 C272 CB6 CB7 D3C1 D3CB2 D3CB5-D3CB7 DCB15-DCB20 DEC1 DEC3 DEC5 DEC7 DEC9 FC1 HC1 HC2 HC9 M1C1-M1C8 M1C11-M1C21 MCB1 PC12 PC17 PC24 PC33 PC35 PC38 PC45 PC47 PC54 PC56 PC62-PC76 PC79 PC88 PC92 PC93 PC99 PC118 PC126 PC128 PC145 PC150 PC170 PC173 SC4 SC7-SC14 SC21 SC22 SC27 SC33 SC36 SC65 SSC4 T1C4 TPC1-TPC4 UC1 UC2 WC5 = DEV_109
C4 C5 SC5 SC6 = DEV_111
C10-C13 C83 C84 C89 = DEV_92
C26 C43 LC16 LC17 PC153 PC169 SSC3 SSC19-SSC22 T1C1 T1C13-T1C15 WC4 = DEV_250
C39-C41 C64 C79-C81 FC2 FC3 PC178-PC193 T1C3 = DEV_249
C85 C86 C153 C252 C255 C307 C308 = DEV_252
C154 C248 = DEV_23
C174 UC3-UC5 = DEV_251
C250 C251 = DEV_262: room: AUD
C941163 PC147 PC163 = DEV_248
CB1 = DEV_91
CB10 CB12 = DEV_22
CE4118 CE4119 = DEV_46
CR6 = DEV_119
D2 D33 = DEV_20
D3 D32 = DEV_21
D3R1-D3R4 FR1 FR5 PR138 PR144 PR170 PR172 R9 R89 R149 R233 R234 R60297-R60299 R60304 R60306 SR5 SR6 SR28 SR112 SR114 SR119 SR120 SR134 SR662 SR663 TPR1 TPR2 TPR5 = DEV_247
D4 = DEV_110
D28 D29 = DEV_18
E4 = DEV_17
E69 = DEV_118
F3 = DEV_35
F3R1-F3R3 MR1 MR2 PR30 PR33 PR43 PR48 PR135 PR152 PR156 R182 R228 R230 SR74 SR110 SR111 SR640 = DEV_246
F3U1 = DEV_39
FD3 FD4 PD2 PD3 SD1 = DEV_19
FD5 = DEV_14
FR3 = DEV_245
FR4 = DEV_244
H1-H4 = DEV_16
H6 H11 = DEV_88
H7 H8 = DEV_116
H9 H10 = DEV_87
H14 = DEV_117
H20-H23 = DEV_76
HR1 HR2 PR119 PR216 PR221 R5 R25 R26 R30 R153 R226 R244 = DEV_104
HR3 HR4 PR121 PR127 = DEV_243
HUBL1 = DEV_106
J8 = DEV_124
J11 = DEV_121
J17 = DEV_270
J27 = DEV_86
J56 = DEV_120
J125 = DEV_268
J133 = DEV_122
J134 = DEV_45
J137 = DEV_75
J218 = DEV_74
J219 = DEV_56
JP4 PJP4 PJP5 = DEV_15
L1-L4 = DEV_114
LC1 LC2 = DEV_242
LL10-LL13 = DEV_105
LR1 MR16 MR17 OP1R3 PR10 PR21 PR54 PR63 PR74 PR76 PR77 PR80 PR85 PR86 PR90 PR95 PR98 PR99 PR104 PR107 PR108 PR113 PR123 PR125 PR131 PR139-PR141 PR143 PR149 PR151 PR164 PR247 R2 R3 R225 R60216 R60307 R60308 SR21 SR22 SR24 SR26 SR31 SR49 SR52 SR64 SR79 SR80 SR82 SR83 SR100-SR104 SR106 SR115-SR118 SR121 SR122 SR193 SR672-SR674 TPR4 WR35 WR36 WR64 WR84 = DEV_99
LR2 = DEV_241
LR62 = DEV_240
LR85 LR87 = DEV_239
LRN11-LRN14 = DEV_3
LU1 = DEV_90
M1R1 M1R2 O2R251 O2R252 PR9 PR15-PR17 PR41 R17 R191 R192 SR4 SR7 SR8 SR13 SR41 SR46 SR66 SR72 SR624 WR34 WR59 WR62 = DEV_101
MD1-MD3 MD5 = DEV_51
MQ33 = DEV_55
MQ34 MQ36 = DEV_73
MQ37 MQ40-MQ42 Q3 WQ6 = DEV_50
MR6-MR13 = DEV_238
MR14 MR15 MR18 MR19 O2R1 R176 SR14 SR16 SR47 SR167 SR170 SR171 SR182-SR185 SR641 = DEV_237
MR24 MR25 O2R240 O2R245-O2R247 OP1R2 PR38 PR49 PR52 PR126 PR133 PR137 PR157 PR159 PR168 PR169 PR183 PR187 R4 R91 R93 R96 R215 R227 R251 R252 R3008 R60218-R60221 R60290 R60302 R60309 SR1 SR2 SR15 SR29 SR34 SR36 SR37 SR65 SR67 SR68 SR71 SR94 SR95 SR109 SR113 SR123 SR124 SR163 SR196 SR625 SR642 SR653-SR656 SR664 SR665 SR670 UR1 UR3 UR7 = DEV_96
MR26 = DEV_236
O2C53 PC13 PC15 PC16 PC25 PC32 PC39 PC42 PC50 PC55 PC77 PC111 PC112 PC114 PC116 PC135 PC138 PC140 PC148 PC160 PC162 PC166 = DEV_235
O2C54 O2C56 O2C59 PC23 PC109 PC134 PC154 PC194 = DEV_234
O2R132 PR118 SR77 SR78 = DEV_233
O2R241 O2R243 O2R244 = DEV_232
O2R242 PR44 R197 R199 R207 R212 R213 R216 R250 R60212 R60215 R60291 R60293 SR35 SR88 SR107 SR108 SR147-SR153 = DEV_72
O2R248 PR177 PR178 PR189 PR190 R188 R60214 = DEV_231
P12 = DEV_11
P13 = DEV_44
P70 = DEV_70
P110 = DEV_71
PC2 = DEV_215
PC3 PC4 PC6 PC10 PC11 PC40 = DEV_230
PC5 PC7 PC8 = DEV_212
PC14 PC124 PC155 = DEV_224
PC18 = DEV_216
PC19-PC22 PC36 PC37 PC105-PC108 PC130-PC133 PC156-PC159 = DEV_48
PC28 = DEV_214
PC31 PC44 PC115 PC139 PC168 = DEV_227
PC34 PC46 = DEV_213
PC48 PC49 PC52 PC57 PC60 PC61 PC80 PC82 PC83 PC85 PC89 PC90 PC96 PC100-PC102 PC113 = DEV_94
PC51 PC94 PC142 = DEV_222
PC84 PC86 PC95 PC97 = DEV_211
PC104 = DEV_229
PC110 = DEV_228
PC117 = DEV_226
PC122 PC144 PC172 = DEV_225
PC136 PC141 = DEV_223
PC143 PC171 = DEV_221
PC146 = DEV_220
PC149 = DEV_219
PC151 PC174 = DEV_218
PC152 PC164 = DEV_217
PCE1 PCE9 PCE10 = DEV_38
PCE2 PCE3 = DEV_68
PCE4 PCE6-PCE8 = DEV_69
PD1 = DEV_10
PJ1 = DEV_53
PJP1 = DEV_40
PJP2 PJP3 PJP6 PJP7 PJP9-PJP16 = DEV_9
PJP8 = DEV_67
PL1-PL4 PL7 PL8 PL10 PL11 PL13 PL14 = DEV_210
PL5 PL6 = DEV_66
PL9 = DEV_82
PL12 = DEV_84
PL15 = DEV_83
PPID1 = DEV_113
PQ1 = DEV_81
PQ2 = DEV_42
PQ4-PQ7 PQ14 PQ23 PQ29 PQ30 PQ47 = DEV_80
PQ8 PQ9 PQ17 PQ20 = DEV_37
PQ10 PQ11 PQ15 PQ18 PQ21 = DEV_6
PQ26 PQ31 PQ45 = DEV_26
PQ41 PQ44 = DEV_36
PQ42 PQ46 = DEV_34
PR1-PR3 PR217 PR219 PR235 PR237 = DEV_209
PR4 = DEV_79
PR5-PR8 = DEV_155
PR11 R90 = DEV_205
PR12 PR13 = DEV_201
PR14 = DEV_193
PR18 PR146 = DEV_190
PR19 PR25 = DEV_181
PR20 PR214 = DEV_178
PR22 = DEV_167
PR23 PR47 PR56 PR57 PR59 PR61 PR65 PR71 PR72 PR83 PR87 PR96 PR106 PR109 PR110 PR115 PR182 PR186 PR196 PR201 PR204 PR222 PR242 R6 R18 R60310 = DEV_100
PR24 = DEV_161
PR26 = DEV_159
PR27 = DEV_63
PR28 PR40 = DEV_158
PR32 PR46 PR191 PR228 = DEV_5
PR35 PR181 = DEV_183
PR36 = DEV_157
PR37 PR50 PR122 R97 = DEV_199
PR39 = DEV_156
PR51 PR60 PR111 = DEV_204
PR53 = DEV_154
PR62 = DEV_153
PR67 PR69 PR81 PR91 PR100 = DEV_208
PR68 PR70 PR78 PR79 PR82 PR88 PR92 PR101 = DEV_207
PR73 PR75 PR84 PR94 PR103 PR165 PR184 PR200 PR215 PR233 PR234 PR241 = DEV_65
PR93 PR102 = DEV_206
PR112 = DEV_203
PR117 PR208 PR225 = DEV_202
PR120 = DEV_200
PR124 = DEV_198
PR129 SR32 = DEV_197
PR132 = DEV_196
PR134 = DEV_195
PR136 R1 R7 R214 R243 R60208 R60209 R60226 = DEV_194
PR142 = DEV_192
PR145 = DEV_191
PR147 = DEV_189
PR148 = DEV_188
PR153 = DEV_64
PR154 = DEV_187
PR158 = DEV_186
PR160 = DEV_185
PR166 PR218 = DEV_184
PR188 PR199 PR223 PR230 = DEV_182
PR192-PR195 = DEV_180
PR198 SR43 = DEV_179
PR202 = DEV_177
PR203 PR236 = DEV_176
PR205 PR238 = DEV_175
PR206 PR239 = DEV_174
PR207 PR240 = DEV_173
PR209 = DEV_172
PR210 = DEV_171
PR211 = DEV_170
PR212 PR245 = DEV_169
PR213 = DEV_168
PR224 PR244 = DEV_166
PR226 = DEV_165
PR229 = DEV_164
PR231 = DEV_163
PR232 = DEV_162
PR243 = DEV_160
PRT1 PRT2 = DEV_152
PRT3-PRT5 = DEV_151
PT1-PT10 ST1-ST3 WT12-WT14 = DEV_49
PU1 = DEV_62
PU2 = DEV_78
PU3 = DEV_61
PU4-PU6 = DEV_29
PU7 = DEV_33
PU8 = DEV_60
PU9 = DEV_24
Q7 = DEV_4
Q27 = DEV_7
R14 R15 = DEV_149
R21 = DEV_98
R22 = DEV_269
R92 SL1-SL8 SL11 SL13 SL14 SL16 = DEV_47
R109 = DEV_150
R159 R169 = DEV_148
R160 R170 = DEV_147
R198 = DEV_54
R200 = DEV_146
R205 R209 = DEV_145
R221 R222 R224 SR48 SR50 SR54 TPR3 = DEV_144
R229 = DEV_8
R330 R332 R357 R368 R370 R371 = DEV_143
R60217 = DEV_112
SC1 SC3 = DEV_142
SM_TP1 = DEV_97
SR9 = DEV_128
SR10 = DEV_141
SR11 = DEV_139
SR18 SR76 = DEV_137
SR30 = DEV_135
SR33 = DEV_134
SR44 = DEV_133
SR55 = DEV_132
SR62 SR626 SR627 = DEV_131
SR63 = DEV_130
SR84 = DEV_129
SR90 SR105 = DEV_140
SR91 = DEV_127
SR98 SR172 = DEV_138
SR188 SR659 = DEV_136
ST4-ST7 ST18-ST20 ST22-ST25 ST29 ST30 ST49 ST50 ST52 ST61 ST69-ST73 ST77-ST89 = DEV_25
SW10 = DEV_93
TPU1 = DEV_59
U1 = DEV_52
U3 U4 = DEV_28
U14 U18 = DEV_32
U19 UU2 = DEV_2
U23 = DEV_89
U24 = DEV_31
U25 = DEV_30
UC6-UC9 UC12-UC15 = DEV_126
UCE1 = DEV_77
UU1 = DEV_1
UU3 = DEV_115
VF1 = DEV_58
WR81 = DEV_125
XBT1 = DEV_123
XMM1 = DEV_43
XU1 = DEV_41
Y5 = DEV_27
Y10 Y12 = DEV_267
Y24 = DEV_266

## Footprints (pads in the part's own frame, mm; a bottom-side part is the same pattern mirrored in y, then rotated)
2MM_OPEN_5MIL_M1M2
  custom 0.318x0.318 smd: 1(0,-0.699) 2(0,0.699)
CESMD_260X260_SMD124X74
  rect 3.15x1.88 smd: 1(2.425,0) 2(-2.425,0)
FPC_26P_20_4HD_RA_PANASONIC
  rect 0.292x0.787 smd: 1(-6.25,2.5) 2(-5.75,2.5) 3(-5.25,2.5) 4(-4.75,2.5) 5(-4.25,2.5) 6(-3.75,2.5) 7(-3.25,2.5) 8(-2.75,2.5) 9(-2.25,2.5) 10(-1.75,2.5) 11(-1.25,2.5) 12(-0.75,2.5) 13(-0.25,2.5) 14(0.25,2.5) 15(0.75,2.5) 16(1.25,2.5) 17(1.75,2.5) 18(2.25,2.5) 19(2.75,2.5) 20(3.25,2.5) 21(3.75,2.5) 22(4.25,2.5) 23(4.75,2.5) 24(5.25,2.5) 25(5.75,2.5) 26(6.25,2.5) 27(-6.75,2.5) 28(6.75,2.5)
  rect 0.406x0.787 smd: 29(-7.75,0) 30(7.75,0)
LAN_CON_14P_4HLD_S_UDE_LF5
  round 2.261 hole 2.261 unplated: (-5.715,0) (5.715,0)
  rect 1.27x1.27 hole 0.864: 1(5.715,6.35)
  round 1.27 hole 0.864: 2(4.445,8.89) 3(3.175,6.35) 4(1.905,8.89) 5(0.635,6.35) 6(-0.635,8.89) 7(-1.905,6.35) 8(-3.175,8.89) 9(-4.445,6.35) 10(-5.715,8.89)
  round 1.372 hole 0.965: 11(6.705,-4.57) 12(6.705,-2.54) 13(-6.705,-4.57) 14(-6.705,-2.54)
  round 2.362 hole 1.6: 15(-7.775,3.05) 16(7.775,3.05)
LB1_LOGO_375X375
  round 0 smd: 1(0,0)
MX_2R4P0603
  rect 0.508x0.838 smd: 1(-0.4,-0.825) 2(-0.4,0.825) 3(0.4,-0.825) 4(0.4,0.825)
MX_BGA_1170P_984X1062
  round 0.521 smd: A3(11.951,-11.814) A52(-12.383,-11.814) B2(12.383,-11.383) B53(-12.814,-11.383) BH1(12.814,11.383) BH53(-12.814,11.383) BJ2(12.383,11.814) BJ52(-12.383,11.814) C1(12.814,-10.951)
  round 0.406 smd: A5(11.17,-11.814) A6(10.447,-11.814) A49(-10.992,-11.814) A51(-11.773,-11.814) B52(-12.225,-11.225) BE1(12.814,9.992) BE53(-12.814,9.992) BG1(12.814,10.773) BG53(-12.814,10.773) BH2(12.225,11.225) BH52(-12.225,11.225) BJ3(11.773,11.814) BJ5(10.992,11.814) BJ49(-10.992,11.814) BJ51(-11.773,11.814) C53(-12.814,-10.773) E1(12.814,-10.17) E53(-12.814,-9.992) F1(12.814,-9.447)
  round 0.356 smd: A7(9.748,-11.814) A9(8.836,-11.814) A47(-9.621,-11.814) A48(-10.294,-11.814) B4(11.632,-11.238) B5(11.038,-11.222) B6(10.445,-11.221) B8(9.258,-11.224) B46(-9.258,-11.224) B48(-10.445,-11.221) B49(-11.038,-11.222) B50(-11.632,-11.238) BC1(12.814,8.621) BC2(12.246,8.852) BC52(-12.246,8.852) BC53(-12.814,8.621) BD1(12.814,9.294) BD2(12.221,9.445) BD52(-12.221,9.445) BD53(-12.814,9.294) BE2(12.222,10.038) BE52(-12.222,10.038) BF2(12.238,10.632) BF52(-12.238,10.632) BG3(11.644,10.644) BG51(-11.644,10.644) BH4(11.632,11.238) BH5(11.038,11.222) BH6(10.445,11.221) BH8(9.258,11.224) BH46(-9.258,11.224) BH48(-10.445,11.221) BH49(-11.038,11.222) BH50(-11.632,11.238) BJ6(10.294,11.814) BJ7(9.621,11.814) BJ47(-9.621,11.814) BJ48(-10.294,11.814) C3(11.644,-10.644) C51(-11.644,-10.644) D2(12.238,-10.632) D52(-12.238,-10.632) E2(12.222,-10.038) E52(-12.222,-10.038) F2(12.221,-9.445) F52(-12.221,-9.445) F53(-12.814,-9.294) G1(12.814,-8.679) G2(12.246,-8.852) G52(-12.246,-8.852) G53(-12.814,-8.621) J1(12.814,-7.816)
  oval 0.254x0.343 smd: A11(7.774,-11.814) A13(6.803,-11.814) A15(5.831,-11.814) A17(4.859,-11.814) A19(3.887,-11.814) A21(2.915,-11.814) A23(1.944,-11.814) A25(0.972,-11.814) A27(0,-11.814) A29(-0.972,-11.814) A31(-1.944,-11.814) A33(-2.915,-11.814) A35(-3.887,-11.814) A37(-4.859,-11.814) A39(-5.831,-11.814) A41(-6.803,-11.814) A43(-7.774,-11.814) A45(-8.746,-11.814) BJ9(8.746,11.814) BJ11(7.774,11.814) BJ13(6.803,11.814) BJ15(5.831,11.814) BJ17(4.859,11.814) BJ19(3.887,11.814) BJ21(2.915,11.814) BJ23(1.944,11.814) BJ25(0.972,11.814) BJ27(0,11.814) BJ29(-0.972,11.814) BJ31(-1.944,11.814) BJ33(-2.915,11.814) BJ35(-3.887,11.814) BJ37(-4.859,11.814) BJ39(-5.831,11.814) BJ41(-6.803,11.814) BJ43(-7.774,11.814) BJ45(-8.746,11.814)
  oval 0.343x0.254 smd: AA1(12.814,-1.944) AA53(-12.814,-1.944) AC1(12.814,-0.972) AC53(-12.814,-0.972) AE1(12.814,0) AE53(-12.814,0) AG1(12.814,0.972) AG53(-12.814,0.972) AJ1(12.814,1.944) AJ53(-12.814,1.944) AL1(12.814,2.915) AL53(-12.814,2.915) AN1(12.814,3.887) AN53(-12.814,3.887) AR1(12.814,4.859) AR53(-12.814,4.859) AU1(12.814,5.831) AU53(-12.814,5.831) AW1(12.814,6.803) AW53(-12.814,6.803) BA1(12.814,7.774) BA53(-12.814,7.774) J53(-12.814,-7.774) L1(12.814,-6.803) L53(-12.814,-6.803) N1(12.814,-5.831) N53(-12.814,-5.831) R1(12.814,-4.859) R53(-12.814,-4.859) U1(12.814,-3.887) U53(-12.814,-3.887) W1(12.814,-2.915) W53(-12.814,-2.915)
  round 0.305 smd: AA3(12.071,-1.944) AA51(-12.071,-1.944) AB4(11.137,-1.448) AB6(10.463,-1.448) AB7(9.752,-1.448) AB9(9.041,-1.448) AB10(8.33,-1.448) AB12(7.618,-1.448) AB13(6.907,-1.448) AB14(6.196,-1.448) AB40(-6.196,-1.448) AB41(-6.907,-1.448) AB42(-7.618,-1.448) AB44(-8.33,-1.448) AB45(-9.041,-1.448) AB47(-9.752,-1.448) AB48(-10.463,-1.448) AB50(-11.137,-1.448) AC51(-12.071,-0.972) AD4(10.995,-0.463) AD6(10.404,-0.525) AD7(9.752,-0.475) AD9(9.041,-0.475) AD10(8.33,-0.475) AD12(7.618,-0.475) AD13(6.907,-0.475) AD14(6.196,-0.475) AD40(-6.196,-0.475) AD41(-6.907,-0.475) AD42(-7.618,-0.475) AD44(-8.33,-0.475) AD45(-9.041,-0.475) AD47(-9.752,-0.475) AD48(-10.404,-0.525) AD50(-10.995,-0.463) AE3(12.071,0) AE6(10.108,0) AE8(9.396,0) AE9(8.685,0) AE11(7.974,0) AE12(7.263,0) AE14(6.552,0) AE40(-6.552,0) AE42(-7.263,0) AE43(-7.974,0) AE45(-8.685,0) AE46(-9.396,0) AE48(-10.108,0) AF4(10.995,0.463) AF6(10.404,0.525) AF7(9.752,0.475) AF9(9.041,0.475) AF10(8.33,0.475) AF12(7.618,0.475) AF13(6.907,0.475) AF14(6.196,0.475) AF40(-6.196,0.475) AF41(-6.907,0.475) AF42(-7.618,0.475) AF44(-8.33,0.475) AF45(-9.041,0.475) AF47(-9.752,0.475) AF48(-10.404,0.525) AF50(-10.995,0.463) AH4(11.137,1.448) AH6(10.463,1.448) AH7(9.752,1.448) AH9(9.041,1.448) AH10(8.33,1.448) AH12(7.618,1.448) AH13(6.907,1.448) AH14(6.196,1.448) AH40(-6.196,1.448) AH41(-6.907,1.448) AH42(-7.618,1.448) AH44(-8.33,1.448) AH45(-9.041,1.448) AH47(-9.752,1.448) AH48(-10.463,1.448) AH50(-11.137,1.448) AK4(11.137,2.439) AK6(10.463,2.439) AK7(9.752,2.439) AK9(9.041,2.439) AK10(8.33,2.439) AK12(7.618,2.439) AK13(6.907,2.439) AK14(6.196,2.439) AK40(-6.196,2.439) AK41(-6.907,2.439) AK42(-7.618,2.439) AK44(-8.33,2.439) AK45(-9.041,2.439) AK47(-9.752,2.439) AK48(-10.463,2.439) AK50(-11.137,2.439) AM4(11.137,3.386) AM6(10.463,3.412) AM7(9.752,3.412) AM9(9.041,3.412) AM10(8.33,3.412) AM12(7.618,3.412) AM13(6.907,3.412) AM14(6.196,3.412) AM40(-6.196,3.412) AM41(-6.907,3.412) AM42(-7.618,3.412) AM44(-8.33,3.412) AM45(-9.041,3.412) AM47(-9.752,3.412) AM48(-10.463,3.412) AM50(-11.137,3.386) AN5(10.819,3.887) AN6(10.108,3.887) AN8(9.396,3.887) AN9(8.685,3.887) AN11(7.974,3.887) AN12(7.263,3.887) AN14(6.552,3.887) AN40(-6.552,3.887) AN42(-7.263,3.887) AN43(-7.974,3.887) AN45(-8.685,3.887) AN46(-9.396,3.887) AN48(-10.108,3.887) AN49(-10.819,3.887) AN51(-12.071,3.887) AP4(11.137,4.388) AP6(10.463,4.362) AP7(9.752,4.362) AP9(9.041,4.362) AP10(8.33,4.362) AP12(7.618,4.362) AP13(6.907,4.362) AP14(6.196,4.362) AP40(-6.196,4.362) AP41(-6.907,4.362) AP42(-7.618,4.362) AP44(-8.33,4.362) AP45(-9.041,4.362) AP47(-9.752,4.362) AP48(-10.463,4.362) AP50(-11.137,4.388) AR51(-12.071,4.859) AT4(11.137,5.336) AT6(10.463,5.336) AT7(9.752,5.336) AT9(9.041,5.336) AT10(8.33,5.336) AT12(7.618,5.336) AT13(6.907,5.336) AT14(6.305,5.336) AT16(5.336,5.196) AT18(4.362,5.196) AT19(3.887,5.552) AT20(3.412,5.196) AT22(2.439,5.196) AT24(1.448,5.196) AT26(0.475,5.196) AT27(0,5.552) AT28(-0.475,5.196) AT30(-1.448,5.196) AT32(-2.439,5.196) AT34(-3.412,5.196) AT35(-3.887,5.552) AT36(-4.362,5.196) AT38(-5.336,5.196) AT40(-6.305,5.336) AT41(-6.907,5.336) AT42(-7.618,5.336) AT44(-8.33,5.336) AT45(-9.041,5.336) AT47(-9.752,5.336) AT48(-10.463,5.336) AT50(-11.137,5.336) AT52(-12.429,5.345) AU16(5.336,5.907) AU18(4.362,5.907) AU20(3.412,5.907) AU22(2.439,5.907) AU24(1.448,5.907) AU26(0.475,5.907) AU28(-0.475,5.907) AU30(-1.448,5.907) AU32(-2.439,5.907) AU34(-3.412,5.907) AU36(-4.362,5.907) AU38(-5.336,5.907) AU51(-12.071,5.831) AV4(11.137,6.326) AV6(10.463,6.326) AV7(9.752,6.326) AV9(9.041,6.326) AV10(8.33,6.326) AV12(7.618,6.326) AV13(6.907,6.326) AV14(6.326,6.446) AV16(5.336,6.618) AV18(4.362,6.618) AV19(3.887,6.263) AV20(3.412,6.618) AV22(2.439,6.618) AV24(1.448,6.618) AV26(0.475,6.618) AV27(0,6.263) AV28(-0.475,6.618) AV30(-1.448,6.618) AV32(-2.439,6.618) AV34(-3.412,6.618) AV35(-3.887,6.263) AV36(-4.362,6.618) AV38(-5.336,6.618) AV40(-6.326,6.446) AV41(-6.907,6.326) AV42(-7.618,6.326) AV44(-8.33,6.326) AV45(-9.041,6.326) AV47(-9.752,6.326) AV48(-10.463,6.326) AV50(-11.137,6.326) AV52(-12.429,6.317) AW3(12.071,6.803) AW13(6.751,6.915) AW19(3.887,6.974) AW27(0,6.974) AW35(-3.887,6.974) AW41(-6.751,6.915) AW51(-12.071,6.803) AY2(12.429,7.289) AY4(11.137,7.317) AY6(10.463,7.317) AY7(9.752,7.317) AY9(9.041,7.317) AY10(8.33,7.317) AY12(7.317,7.34) AY14(6.326,7.33) AY16(5.336,7.33) AY18(4.362,7.33) AY20(3.412,7.33) AY22(2.439,7.33) AY24(1.448,7.33) AY26(0.475,7.33) AY28(-0.475,7.33) AY30(-1.448,7.33) AY32(-2.439,7.33) AY34(-3.412,7.33) AY36(-4.362,7.33) AY38(-5.336,7.33) AY40(-6.326,7.33) AY42(-7.317,7.34) AY44(-8.33,7.317) AY45(-9.041,7.317) AY47(-9.752,7.317) AY48(-10.463,7.317) AY50(-11.137,7.317) AY52(-12.429,7.289) B7(9.852,-11.23) B14(6.317,-11.429) B30(-1.458,-11.429) B44(-8.26,-11.429) B47(-9.852,-11.23) BA12(7.317,8.041) BA14(6.326,8.041) BA16(5.336,8.041) BA18(4.362,8.041) BA19(3.887,7.685) BA20(3.412,8.041) BA22(2.439,8.041) BA24(1.448,8.041) BA26(0.475,8.041) BA27(0,7.685) BA28(-0.475,8.041) BA30(-1.448,8.041) BA32(-2.439,8.041) BA34(-3.412,8.041) BA35(-3.887,7.685) BA36(-4.362,8.041) BA38(-5.336,8.041) BA40(-6.326,8.041) BA42(-7.317,8.041) BA51(-12.071,7.774) BB4(11.258,8.307) BB5(10.547,8.307) BB7(9.835,8.307) BB8(9.124,8.307) BB10(8.307,8.17) BB19(3.887,8.396) BB27(0,8.396) BB35(-3.887,8.396) BB44(-8.307,8.17) BB46(-9.124,8.307) BB47(-9.835,8.307) BB49(-10.547,8.307) BB50(-11.258,8.307) BC10(8.307,8.764) BC12(7.317,8.752) BC14(6.326,8.752) BC16(5.336,8.752) BC18(4.362,8.752) BC20(3.412,8.752) BC22(2.439,8.752) BC24(1.448,8.752) BC26(0.475,8.752) BC28(-0.475,8.752) BC30(-1.448,8.752) BC32(-2.439,8.752) BC34(-3.412,8.752) BC36(-4.362,8.752) BC38(-5.336,8.752) BC40(-6.326,8.752) BC42(-7.317,8.752) BC44(-8.307,8.764) BD5(10.565,9.302) BD7(9.712,9.302) BD10(8.307,9.457) BD12(7.317,9.463) BD14(6.326,9.463) BD16(5.336,9.463) BD18(4.362,9.463) BD19(3.887,9.108) BD20(3.412,9.463) BD22(2.439,9.463) BD24(1.448,9.463) BD26(0.525,9.404) BD27(0,9.108) BD28(-0.525,9.404) BD30(-1.448,9.463) BD32(-2.439,9.463) BD34(-3.412,9.463) BD35(-3.887,9.108) BD36(-4.362,9.463) BD38(-5.336,9.463) BD40(-6.326,9.463) BD42(-7.317,9.463) BD44(-8.307,9.457) BD47(-9.712,9.302) BD49(-10.565,9.302) BE3(11.643,9.58) BE8(9.32,9.747) BE19(3.887,9.819) BE35(-3.887,9.819) BE46(-9.32,9.747) BE51(-11.643,9.58) BF4(11.163,10.163) BF6(10.113,10.238) BF10(8.307,10.168) BF12(7.317,10.137) BF14(6.326,10.137) BF16(5.336,10.137) BF18(4.388,10.137) BF20(3.386,10.137) BF22(2.439,10.137) BF24(1.448,10.137) BF26(0.463,9.995) BF28(-0.463,9.995) BF30(-1.448,10.137) BF32(-2.439,10.137) BF34(-3.386,10.137) BF36(-4.388,10.137) BF38(-5.336,10.137) BF40(-6.326,10.137) BF42(-7.317,10.137) BF44(-8.307,10.168) BF48(-10.113,10.238) BF50(-11.163,10.163) BG5(10.58,10.643) BG7(9.553,10.709) BG9(8.698,11.028) BG11(7.774,11.071) BG25(0.972,11.071) BG31(-1.944,11.071) BG39(-5.831,11.071) BG41(-6.803,11.071) BG43(-7.774,11.071) BG45(-8.698,11.028) BG47(-9.553,10.709) BG49(-10.58,10.643) BH7(9.852,11.23) BH24(1.458,11.429) BH26(0.486,11.429) BH28(-0.486,11.429) BH36(-4.373,11.429) BH42(-7.289,11.429) BH44(-8.26,11.429) BH47(-9.852,11.23) C5(10.58,-10.643) C7(9.553,-10.709) C9(8.698,-11.028) C31(-1.944,-11.071) C47(-9.553,-10.709) C49(-10.58,-10.643) D4(11.163,-10.163) D6(10.113,-10.238) D10(8.307,-10.168) D12(7.317,-10.137) D14(6.326,-10.137) D16(5.336,-10.137) D18(4.388,-10.137) D20(3.386,-10.137) D22(2.439,-10.137) D24(1.448,-10.137) D26(0.463,-9.995) D28(-0.463,-9.995) D30(-1.448,-10.137) D32(-2.439,-10.137) D34(-3.386,-10.137) D36(-4.388,-10.137) D38(-5.336,-10.137) D40(-6.326,-10.137) D42(-7.317,-10.137) D44(-8.307,-10.168) D48(-10.113,-10.238) D50(-11.163,-10.163) E3(11.643,-9.58) E8(9.32,-9.747) E19(3.887,-9.819) E35(-3.887,-9.819) E46(-9.32,-9.747) E51(-11.643,-9.58) F5(10.565,-9.302) F7(9.712,-9.302) F10(8.307,-9.457) F12(7.317,-9.463) F14(6.326,-9.463) F16(5.336,-9.463) F18(4.362,-9.463) F19(3.887,-9.108) F20(3.412,-9.463) F22(2.439,-9.463) F24(1.448,-9.463) F26(0.525,-9.404) F27(0,-9.108) F28(-0.525,-9.404) F30(-1.448,-9.463) F32(-2.439,-9.463) F34(-3.412,-9.463) F35(-3.887,-9.108) F36(-4.362,-9.463) F38(-5.336,-9.463) F40(-6.326,-9.463) F42(-7.317,-9.463) F44(-8.307,-9.457) F47(-9.712,-9.302) F49(-10.565,-9.302) G10(8.307,-8.764) G12(7.317,-8.752) G14(6.326,-8.752) G16(5.336,-8.752) G18(4.362,-8.752) G20(3.412,-8.752) G22(2.439,-8.752) G24(1.448,-8.752) G26(0.475,-8.752) G28(-0.475,-8.752) G30(-1.448,-8.752) G32(-2.439,-8.752) G34(-3.412,-8.752) G36(-4.362,-8.752) G38(-5.336,-8.752) G40(-6.326,-8.752) G42(-7.317,-8.752) G44(-8.307,-8.764) H4(11.258,-8.307) H5(10.547,-8.307) H7(9.835,-8.307) H8(9.124,-8.307) H10(8.307,-8.17) H19(3.887,-8.396) H27(0,-8.396) H35(-3.887,-8.396) H44(-8.307,-8.17) H46(-9.124,-8.307) H47(-9.835,-8.307) H49(-10.547,-8.307) H50(-11.258,-8.307) J3(12.071,-7.774) J12(7.317,-8.041) J14(6.326,-8.041) J16(5.336,-8.041) J18(4.362,-8.041) J19(3.887,-7.685) J20(3.412,-8.041) J22(2.439,-8.041) J24(1.448,-8.041) J26(0.475,-8.041) J27(0,-7.685) J28(-0.475,-8.041) J30(-1.448,-8.041) J32(-2.439,-8.041) J34(-3.412,-8.041) J35(-3.887,-7.685) J36(-4.362,-8.041) J38(-5.336,-8.041) J40(-6.326,-8.041) J42(-7.317,-8.041) K4(11.137,-7.317) K6(10.463,-7.317) K7(9.752,-7.317) K9(9.041,-7.317) K10(8.33,-7.317) K12(7.317,-7.34) K14(6.326,-7.33) K16(5.336,-7.33) K18(4.362,-7.33) K20(3.412,-7.33) K22(2.439,-7.33) K24(1.448,-7.33) K26(0.475,-7.33) K28(-0.475,-7.33) K30(-1.448,-7.33) K32(-2.439,-7.33) K34(-3.412,-7.33) K36(-4.362,-7.33) K38(-5.336,-7.33) K40(-6.326,-7.33) K42(-7.317,-7.34) K44(-8.33,-7.317) K45(-9.041,-7.317) K47(-9.752,-7.317) K48(-10.463,-7.317) K50(-11.137,-7.317) L13(6.751,-6.915) L19(3.887,-6.974) L27(0,-6.974) L35(-3.887,-6.974) L41(-6.751,-6.915) M2(12.429,-6.317) M4(11.137,-6.326) M6(10.463,-6.326) M7(9.752,-6.326) M9(9.041,-6.326) M10(8.33,-6.326) M12(7.618,-6.326) M13(6.907,-6.326) M14(6.326,-6.446) M16(5.336,-6.618) M18(4.362,-6.618) M19(3.887,-6.263) M20(3.412,-6.618) M22(2.439,-6.618) M24(1.448,-6.618) M26(0.475,-6.618) M27(0,-6.263) M28(-0.475,-6.618) M30(-1.448,-6.618) M32(-2.439,-6.618) M34(-3.412,-6.618) M35(-3.887,-6.263) M36(-4.362,-6.618) M38(-5.336,-6.618) M40(-6.326,-6.446) M41(-6.907,-6.326) M42(-7.618,-6.326) M44(-8.33,-6.326) M45(-9.041,-6.326) M47(-9.752,-6.326) M48(-10.463,-6.326) M50(-11.137,-6.326) N16(5.336,-5.907) N18(4.362,-5.907) N20(3.412,-5.907) N22(2.439,-5.907) N24(1.448,-5.907) N26(0.475,-5.907) N28(-0.475,-5.907) N30(-1.448,-5.907) N32(-2.439,-5.907) N34(-3.412,-5.907) N36(-4.362,-5.907) N38(-5.336,-5.907) N51(-12.071,-5.831) P4(11.137,-5.336) P6(10.463,-5.336) P7(9.752,-5.336) P9(9.041,-5.336) P10(8.33,-5.336) P12(7.618,-5.336) P13(6.907,-5.336) P14(6.305,-5.336) P16(5.336,-5.196) P18(4.362,-5.196) P19(3.887,-5.552) P20(3.412,-5.196) P22(2.439,-5.196) P24(1.448,-5.196) P26(0.475,-5.196) P27(0,-5.552) P28(-0.475,-5.196) P30(-1.448,-5.196) P32(-2.439,-5.196) P34(-3.412,-5.196) P35(-3.887,-5.552) P36(-4.362,-5.196) P38(-5.336,-5.196) P40(-6.305,-5.336) P41(-6.907,-5.336) P42(-7.618,-5.336) P44(-8.33,-5.336) P45(-9.041,-5.336) P47(-9.752,-5.336) P48(-10.463,-5.336) P50(-11.137,-5.336) T4(11.137,-4.388) T6(10.463,-4.362) T7(9.752,-4.362) T9(9.041,-4.362) T10(8.33,-4.362) T12(7.618,-4.362) T13(6.907,-4.362) T14(6.196,-4.362) T40(-6.196,-4.362) T41(-6.907,-4.362) T42(-7.618,-4.362) T44(-8.33,-4.362) T45(-9.041,-4.362) T47(-9.752,-4.362) T48(-10.463,-4.362) T50(-11.137,-4.388) U3(12.071,-3.887) U5(10.819,-3.887) U6(10.108,-3.887) U8(9.396,-3.887) U9(8.685,-3.887) U11(7.974,-3.887) U12(7.263,-3.887) U14(6.552,-3.887) U40(-6.552,-3.887) U42(-7.263,-3.887) U43(-7.974,-3.887) U45(-8.685,-3.887) U46(-9.396,-3.887) U48(-10.108,-3.887) U49(-10.819,-3.887) V2(12.429,-3.401) V4(11.137,-3.386) V6(10.463,-3.412) V7(9.752,-3.412) V9(9.041,-3.412) V10(8.33,-3.412) V12(7.618,-3.412) V13(6.907,-3.412) V14(6.196,-3.412) V40(-6.196,-3.412) V41(-6.907,-3.412) V42(-7.618,-3.412) V44(-8.33,-3.412) V45(-9.041,-3.412) V47(-9.752,-3.412) V48(-10.463,-3.412) V50(-11.137,-3.386) Y2(12.429,-2.43) Y4(11.137,-2.439) Y6(10.463,-2.439) Y7(9.752,-2.439) Y9(9.041,-2.439) Y10(8.33,-2.439) Y12(7.618,-2.439) Y13(6.907,-2.439) Y14(6.196,-2.439) Y40(-6.196,-2.439) Y41(-6.907,-2.439) Y42(-7.618,-2.439) Y44(-8.33,-2.439) Y45(-9.041,-2.439) Y47(-9.752,-2.439) Y48(-10.463,-2.439) Y50(-11.137,-2.439)
  round 0.33 smd: AA16(5.307,-1.961) AA18(4.549,-1.961) AA19(3.791,-1.961) AA21(3.033,-1.961) AA22(2.275,-1.961) AA24(1.516,-1.961) AA25(0.758,-1.961) AA27(0,-1.961) AA29(-0.758,-1.961) AA30(-1.516,-1.961) AA32(-2.275,-1.961) AA33(-3.033,-1.961) AA35(-3.791,-1.961) AA36(-4.549,-1.961) AA38(-5.307,-1.961) AC16(5.307,-1.177) AC18(4.549,-1.177) AC19(3.791,-1.177) AC21(3.033,-1.177) AC22(2.275,-1.177) AC24(1.516,-1.177) AC25(0.758,-1.177) AC27(0,-1.177) AC29(-0.758,-1.177) AC30(-1.516,-1.177) AC32(-2.275,-1.177) AC33(-3.033,-1.177) AC35(-3.791,-1.177) AC36(-4.549,-1.177) AC38(-5.307,-1.177) AD16(5.307,-0.392) AD18(4.549,-0.392) AD19(3.791,-0.392) AD21(3.033,-0.392) AD22(2.275,-0.392) AD24(1.516,-0.392) AD25(0.758,-0.392) AD27(0,-0.392) AD29(-0.758,-0.392) AD30(-1.516,-0.392) AD32(-2.275,-0.392) AD33(-3.033,-0.392) AD35(-3.791,-0.392) AD36(-4.549,-0.392) AD38(-5.307,-0.392) AF16(5.307,0.392) AF18(4.549,0.392) AF19(3.791,0.392) AF21(3.033,0.392) AF22(2.275,0.392) AF24(1.516,0.392) AF25(0.758,0.392) AF27(0,0.392) AF29(-0.758,0.392) AF30(-1.516,0.392) AF32(-2.275,0.392) AF33(-3.033,0.392) AF35(-3.791,0.392) AF36(-4.549,0.392) AF38(-5.307,0.392) AG16(5.307,1.177) AG18(4.549,1.177) AG19(3.791,1.177) AG21(3.033,1.177) AG22(2.275,1.177) AG24(1.516,1.177) AG25(0.758,1.177) AG27(0,1.177) AG29(-0.758,1.177) AG30(-1.516,1.177) AG32(-2.275,1.177) AG33(-3.033,1.177) AG35(-3.791,1.177) AG36(-4.549,1.177) AG38(-5.307,1.177) AJ16(5.307,1.961) AJ18(4.549,1.961) AJ19(3.791,1.961) AJ21(3.033,1.961) AJ22(2.275,1.961) AJ24(1.516,1.961) AJ25(0.758,1.961) AJ27(0,1.961) AJ29(-0.758,1.961) AJ30(-1.516,1.961) AJ32(-2.275,1.961) AJ33(-3.033,1.961) AJ35(-3.791,1.961) AJ36(-4.549,1.961) AJ38(-5.307,1.961) AK16(5.307,2.745) AK18(4.549,2.745) AK19(3.791,2.745) AK21(3.033,2.745) AK22(2.275,2.745) AK24(1.516,2.745) AK25(0.758,2.745) AK27(0,2.745) AK29(-0.758,2.745) AK30(-1.516,2.745) AK32(-2.275,2.745) AK33(-3.033,2.745) AK35(-3.791,2.745) AK36(-4.549,2.745) AK38(-5.307,2.745) AM16(5.307,3.53) AM18(4.549,3.53) AM19(3.791,3.53) AM21(3.033,3.53) AM22(2.275,3.53) AM24(1.516,3.53) AM25(0.758,3.53) AM27(0,3.53) AM29(-0.758,3.53) AM30(-1.516,3.53) AM32(-2.275,3.53) AM33(-3.033,3.53) AM35(-3.791,3.53) AM36(-4.549,3.53) AM38(-5.307,3.53) AN16(5.307,4.314) AN18(4.549,4.314) AN19(3.791,4.314) AN21(3.033,4.314) AN22(2.275,4.314) AN24(1.516,4.314) AN25(0.758,4.314) AN27(0,4.314) AN29(-0.758,4.314) AN30(-1.516,4.314) AN32(-2.275,4.314) AN33(-3.033,4.314) AN35(-3.791,4.314) AN36(-4.549,4.314) AN38(-5.307,4.314) U16(5.307,-4.314) U18(4.549,-4.314) U19(3.791,-4.314) U21(3.033,-4.314) U22(2.275,-4.314) U24(1.516,-4.314) U25(0.758,-4.314) U27(0,-4.314) U29(-0.758,-4.314) U30(-1.516,-4.314) U32(-2.275,-4.314) U33(-3.033,-4.314) U35(-3.791,-4.314) U36(-4.549,-4.314) U38(-5.307,-4.314) V16(5.307,-3.53) V18(4.549,-3.53) V19(3.791,-3.53) V21(3.033,-3.53) V22(2.275,-3.53) V24(1.516,-3.53) V25(0.758,-3.53) V27(0,-3.53) V29(-0.758,-3.53) V30(-1.516,-3.53) V32(-2.275,-3.53) V33(-3.033,-3.53) V35(-3.791,-3.53) V36(-4.549,-3.53) V38(-5.307,-3.53) Y16(5.307,-2.745) Y18(4.549,-2.745) Y19(3.791,-2.745) Y21(3.033,-2.745) Y22(2.275,-2.745) Y24(1.516,-2.745) Y25(0.758,-2.745) Y27(0,-2.745) Y29(-0.758,-2.745) Y30(-1.516,-2.745) Y32(-2.275,-2.745) Y33(-3.033,-2.745) Y35(-3.791,-2.745) Y36(-4.549,-2.745) Y38(-5.307,-2.745)
  round 0.279 smd: AB2(12.429,-1.458) AB3(11.73,-1.458) AB51(-11.73,-1.458) AB52(-12.429,-1.458) AC3(12.071,-0.972) AD2(12.429,-0.486) AD3(11.715,-0.48) AD51(-11.715,-0.48) AD52(-12.429,-0.486) AE4(11.366,0) AE50(-11.366,0) AE51(-12.071,0) AF2(12.429,0.486) AF3(11.715,0.48) AF51(-11.715,0.48) AF52(-12.429,0.486) AG3(12.071,0.972) AG51(-12.071,0.972) AH2(12.429,1.458) AH3(11.73,1.458) AH51(-11.73,1.458) AH52(-12.429,1.458) AJ3(12.071,1.944) AJ51(-12.071,1.944) AK2(12.429,2.43) AK3(11.73,2.43) AK51(-11.73,2.43) AK52(-12.429,2.43) AL3(12.071,2.915) AL51(-12.071,2.915) AM2(12.429,3.401) AM3(11.73,3.401) AM51(-11.73,3.401) AM52(-12.429,3.401) AN3(12.071,3.887) AP2(12.429,4.373) AP3(11.73,4.373) AP51(-11.73,4.373) AP52(-12.429,4.373) AR3(12.071,4.859) AT2(12.429,5.345) AT3(11.73,5.345) AT51(-11.73,5.345) AU3(12.071,5.831) AV2(12.429,6.317) AV3(11.73,6.317) AV51(-11.73,6.317) AY3(11.73,7.289) AY51(-11.73,7.289) B10(8.26,-11.429) B12(7.289,-11.429) B16(5.345,-11.429) B18(4.373,-11.429) B20(3.401,-11.429) B22(2.43,-11.429) B24(1.458,-11.429) B26(0.486,-11.429) B28(-0.486,-11.429) B32(-2.43,-11.429) B34(-3.401,-11.429) B36(-4.373,-11.429) B38(-5.345,-11.429) B40(-6.317,-11.429) B42(-7.289,-11.429) BA3(12.071,7.774) BB3(11.929,8.351) BB51(-11.929,8.351) BF27(0,10.366) BG12(7.289,10.73) BG13(6.803,11.071) BG14(6.317,10.73) BG15(5.831,11.071) BG16(5.345,10.73) BG17(4.859,11.071) BG18(4.373,10.73) BG19(3.887,11.071) BG20(3.401,10.73) BG21(2.915,11.071) BG22(2.43,10.73) BG23(1.944,11.071) BG24(1.458,10.73) BG26(0.48,10.715) BG27(0,11.071) BG28(-0.48,10.715) BG29(-0.972,11.071) BG30(-1.458,10.73) BG32(-2.43,10.73) BG33(-2.915,11.071) BG34(-3.401,10.73) BG35(-3.887,11.071) BG36(-4.373,10.73) BG37(-4.859,11.071) BG38(-5.345,10.73) BG40(-6.317,10.73) BG42(-7.289,10.73) BH10(8.26,11.429) BH12(7.289,11.429) BH14(6.317,11.429) BH16(5.345,11.429) BH18(4.373,11.429) BH20(3.401,11.429) BH22(2.43,11.429) BH30(-1.458,11.429) BH32(-2.43,11.429) BH34(-3.401,11.429) BH38(-5.345,11.429) BH40(-6.317,11.429) C11(7.774,-11.071) C12(7.289,-10.73) C13(6.803,-11.071) C14(6.317,-10.73) C15(5.831,-11.071) C16(5.345,-10.73) C17(4.859,-11.071) C18(4.373,-10.73) C19(3.887,-11.071) C20(3.401,-10.73) C21(2.915,-11.071) C22(2.43,-10.73) C23(1.944,-11.071) C24(1.458,-10.73) C25(0.972,-11.071) C26(0.48,-10.715) C27(0,-11.071) C28(-0.48,-10.715) C29(-0.972,-11.071) C30(-1.458,-10.73) C32(-2.43,-10.73) C33(-2.915,-11.071) C34(-3.401,-10.73) C35(-3.887,-11.071) C36(-4.373,-10.73) C37(-4.859,-11.071) C38(-5.345,-10.73) C39(-5.831,-11.071) C40(-6.317,-10.73) C41(-6.803,-11.071) C42(-7.289,-10.73) C43(-7.774,-11.071) C45(-8.698,-11.028) D27(0,-10.366) H3(11.929,-8.351) H51(-11.929,-8.351) J51(-12.071,-7.774) K2(12.429,-7.289) K3(11.73,-7.289) K51(-11.73,-7.289) K52(-12.429,-7.289) L3(12.071,-6.803) L51(-12.071,-6.803) M3(11.73,-6.317) M51(-11.73,-6.317) M52(-12.429,-6.317) N3(12.071,-5.831) P2(12.429,-5.345) P3(11.73,-5.345) P51(-11.73,-5.345) P52(-12.429,-5.345) R3(12.071,-4.859) R51(-12.071,-4.859) T2(12.429,-4.373) T3(11.73,-4.373) T51(-11.73,-4.373) T52(-12.429,-4.373) U51(-12.071,-3.887) V3(11.73,-3.401) V51(-11.73,-3.401) V52(-12.429,-3.401) W3(12.071,-2.915) W51(-12.071,-2.915) Y3(11.73,-2.43) Y51(-11.73,-2.43) Y52(-12.429,-2.43)
